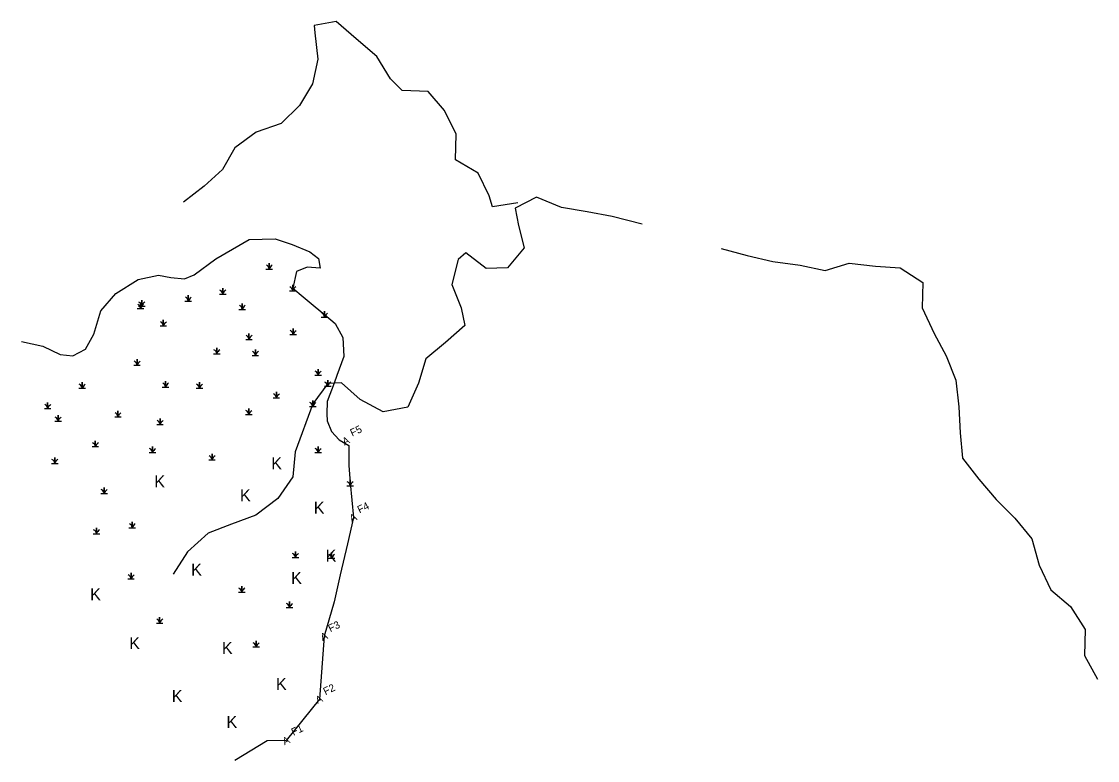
# Model space of a CAD drawing. Extents: x 2171061 to 2188174, y 801741 to 821647.
# Drawn here: x 2186425 to 2187134, y 817904 to 818392 of the extents above; entities that cross this region are included whole.
import ezdxf

# ---------------------------------------------------------------- set-up
doc = ezdxf.new("R2010")
doc.units = 0
for name, color, linetype in [('Exist Environmental Wetland Boundary', 7, 'Continuous'), ('Exist Hydro Jurisdictional Stream or Body of Water NEU Mitigable', 7, 'Continuous'), ('Exist Hydro Swamp or Marsh', 7, 'Continuous'), ('Old_Level_10', 7, 'Continuous'), ('Old_Level_20', 7, 'Continuous'), ('Old_Level_61', 7, 'Continuous')]:
    doc.layers.add(name, color=color, linetype=linetype)

msp = doc.modelspace()

# ---------------------------------------------------------------- linework, layer by layer
at = {"layer": 'Exist Environmental Wetland Boundary'}
msp.add_lwpolyline([(2186425.42, 818180.61), (2186439.36, 818177.5), (2186450.84, 818172.08), (2186459.21, 818171.26), (2186467.58, 818175.69), (2186473.15, 818185.54), (2186477.75, 818200.79), (2186487.59, 818212.27), (2186502.19, 818221.62), (2186515.64, 818224.41), (2186523.68, 818222.94), (2186532.7, 818221.95), (2186539.26, 818224.58), (2186553.53, 818235.24), (2186553.53, 818235.24), (2186575.35, 818247.87), (2186592.58, 818248.36), (2186603.73, 818244.59), (2186615.38, 818239.83), (2186621.12, 818235.4), (2186622.1, 818229.01), (2186613.57, 818229.66), (2186606.52, 818226.87), (2186604.06, 818215.88), (2186610.95, 818210.14), (2186618.82, 818203.58), (2186625.06, 818198.49), (2186631.95, 818192.59), (2186637.03, 818183.24), (2186637.69, 818170.77), (2186633.09, 818158.3), (2186631.29, 818153.22), (2186626.86, 818141.08), (2186626.53, 818133.04), (2186626.86, 818128.29), (2186629.65, 818121.4), (2186634.74, 818115.82), (2186640.97, 818112.04), (2186641.08, 818098.82), (2186641.89, 818087.39), (2186644.07, 818064.67), (2186644.07, 818064.67), (2186640.26, 818047.38), (2186635.37, 818026.96), (2186631.29, 818009), (2186624.86, 817986.4), (2186621.62, 817944.9), (2186599.84, 817917.73), (2186587.16, 817917.49), (2186566.03, 817904.48)], dxfattribs=at)
at = {"layer": 'Exist Hydro Jurisdictional Stream or Body of Water NEU Mitigable'}
for points in [[(2186752.35, 818271.99), (2186735.78, 818269.36), (2186733.49, 818276.58), (2186726.27, 818291.67), (2186711.34, 818300.36), (2186711.67, 818317.26), (2186704.12, 818332.84), (2186693.3, 818345.48), (2186676.24, 818346.13), (2186668.53, 818353.84), (2186659.5, 818368.44), (2186645.89, 818380.09), (2186632.6, 818391.57), (2186618.24, 818388.84), (2186618.66, 818384.19), (2186620.63, 818366.8), (2186617.02, 818350.4), (2186608.49, 818336.13), (2186596.51, 818324.31), (2186579.94, 818318.57), (2186566, 818308.4), (2186557.8, 818294.13), (2186545.82, 818283.14), (2186532.04, 818272.48)], [(2186834.21, 818258.04), (2186814.52, 818263.13), (2186798.12, 818266.08), (2186781.06, 818269.03), (2186764.66, 818275.76), (2186750.55, 818268.54), (2186752.85, 818257.22), (2186756.62, 818242.29), (2186745.63, 818229.17), (2186731.52, 818228.68), (2186718.23, 818239.01), (2186712.98, 818234.75), (2186708.88, 818218.18), (2186715.12, 818202.92), (2186717.41, 818191.28), (2186704.62, 818179.96), (2186691.82, 818169.3), (2186686.9, 818153.22), (2186680.01, 818137.31), (2186663.77, 818134.35), (2186648.51, 818142.39), (2186636.21, 818153.38), (2186627.19, 818153.06), (2186617.35, 818139.6), (2186605.7, 818107.94), (2186604.06, 818091.54), (2186594.38, 818077.27), (2186579.78, 818066.28), (2186563.71, 818060.21), (2186548.28, 818054.3), (2186534.83, 818042), (2186525.32, 818027.4)], [(2186886.37, 818241.97), (2186903.43, 818237.37), (2186920.33, 818233.44), (2186938.38, 818230.98), (2186954.94, 818227.53), (2186970.69, 818232.29), (2186987.92, 818230.32), (2187004.32, 818229.17), (2187019.08, 818219.49), (2187018.76, 818202.76), (2187026.63, 818185.86), (2187034.5, 818171.1), (2187040.9, 818155.19), (2187042.87, 818137.64), (2187043.69, 818120.41), (2187045.33, 818103.68), (2187055.99, 818089.9), (2187067.48, 818076.45), (2187079.78, 818064.31), (2187091.1, 818050.69), (2187095.86, 818033.14), (2187103.57, 818017.06), (2187116.36, 818006.07), (2187126.04, 817990.82), (2187125.71, 817973.76), (2187134.24, 817958.17)]]:
    msp.add_lwpolyline(points, dxfattribs=at)
at = {"layer": 'Exist Hydro Swamp or Marsh'}
for p, q in [((2186588.61, 818230.18), (2186588.61, 818230.18)), ((2186558, 818213.68), (2186558, 818213.68)), ((2186604.06, 818215.88), (2186604.06, 818215.88)), ((2186503.85, 818204.25), (2186503.85, 818204.25)), ((2186504.63, 818205.82), (2186504.63, 818205.82)), ((2186535.24, 818208.97), (2186535.24, 818208.97)), ((2186570.81, 818203.61), (2186570.81, 818203.61)), ((2186625.06, 818198.49), (2186625.06, 818198.49)), ((2186518.84, 818192.78), (2186518.84, 818192.78)), ((2186575.27, 818183.83), (2186575.27, 818183.83)), ((2186604.31, 818186.97), (2186604.31, 818186.97)), ((2186554.08, 818174.4), (2186554.08, 818174.4)), ((2186579.47, 818173.27), (2186579.47, 818173.27)), ((2186501.52, 818166.77), (2186501.52, 818166.77)), ((2186620.79, 818160.26), (2186620.79, 818160.26)), ((2186620.79, 818160.26), (2186620.79, 818160.26)), ((2186465.39, 818151.61), (2186465.39, 818151.61)), ((2186520.33, 818152.4), (2186520.33, 818152.4)), ((2186542.66, 818151.6), (2186542.66, 818151.6)), ((2186627.19, 818153.06), (2186627.19, 818153.06)), ((2186593.32, 818145.33), (2186593.32, 818145.33)), ((2186442.63, 818138.26), (2186442.63, 818138.26)), ((2186488.94, 818132.76), (2186488.94, 818132.76)), ((2186575.14, 818134.26), (2186575.14, 818134.26)), ((2186617.35, 818139.6), (2186617.35, 818139.6)), ((2186449.55, 818129.92), (2186449.55, 818129.92)), ((2186516.68, 818127.75), (2186516.68, 818127.75)), ((2186474.03, 818113.12), (2186474.03, 818113.12)), ((2186511.7, 818109.19), (2186511.7, 818109.19)), ((2186550.94, 818104.48), (2186550.94, 818104.48)), ((2186620.79, 818109.19), (2186620.79, 818109.19)), ((2186447.34, 818102.12), (2186447.34, 818102.12)), ((2186641.89, 818087.39), (2186641.89, 818087.39)), ((2186479.87, 818082.24), (2186479.87, 818082.24)), ((2186479.87, 818082.24), (2186479.87, 818082.24)), ((2186474.81, 818055.77), (2186474.81, 818055.77)), ((2186498.36, 818059.69), (2186498.36, 818059.69)), ((2186605.88, 818040.05), (2186605.88, 818040.05)), ((2186629.68, 818039.51), (2186629.68, 818039.51)), ((2186497.57, 818025.91), (2186497.57, 818025.91)), ((2186570.56, 818017.27), (2186570.56, 818017.27)), ((2186601.96, 818007.06), (2186601.96, 818007.06)), ((2186516.41, 817996.84), (2186516.41, 817996.84)), ((2186579.98, 817981.13), (2186579.98, 817981.13))]:
    msp.add_line(p, q, dxfattribs=at)
for points in [[(2186586.46, 818228.4), (2186588.61, 818228.4), (2186588.61, 818232.34), (2186588.61, 818228.4), (2186590.76, 818228.4)], [(2186601.91, 818214.1), (2186604.06, 818214.1), (2186604.06, 818218.05), (2186604.06, 818214.1), (2186606.21, 818214.1)], [(2186533.09, 818207.18), (2186535.24, 818207.18), (2186535.24, 818211.13), (2186535.24, 818207.18), (2186537.39, 818207.18)], [(2186555.85, 818211.9), (2186558, 818211.9), (2186558, 818215.84), (2186558, 818211.9), (2186560.15, 818211.9)], [(2186501.7, 818202.47), (2186503.85, 818202.47), (2186503.85, 818206.41), (2186503.85, 818202.47), (2186506, 818202.47)], [(2186502.48, 818204.04), (2186504.63, 818204.04), (2186504.63, 818207.99), (2186504.63, 818204.04), (2186506.79, 818204.04)], [(2186568.66, 818201.83), (2186570.81, 818201.83), (2186570.81, 818205.78), (2186570.81, 818201.83), (2186572.96, 818201.83)], [(2186622.91, 818196.71), (2186625.06, 818196.71), (2186625.06, 818200.66), (2186625.06, 818196.71), (2186627.21, 818196.71)], [(2186516.69, 818190.99), (2186518.84, 818190.99), (2186518.84, 818194.94), (2186518.84, 818190.99), (2186520.99, 818190.99)], [(2186573.12, 818182.04), (2186575.27, 818182.04), (2186575.27, 818185.99), (2186575.27, 818182.04), (2186577.42, 818182.04)], [(2186602.16, 818185.19), (2186604.31, 818185.19), (2186604.31, 818189.13), (2186604.31, 818185.19), (2186606.46, 818185.19)], [(2186551.93, 818172.62), (2186554.08, 818172.62), (2186554.08, 818176.56), (2186554.08, 818172.62), (2186556.23, 818172.62)], [(2186577.32, 818171.49), (2186579.47, 818171.49), (2186579.47, 818175.43), (2186579.47, 818171.49), (2186581.62, 818171.49)], [(2186499.37, 818164.98), (2186501.52, 818164.98), (2186501.52, 818168.93), (2186501.52, 818164.98), (2186503.67, 818164.98)], [(2186618.64, 818158.47), (2186620.79, 818158.47), (2186620.79, 818162.42), (2186620.79, 818158.47), (2186622.94, 818158.47)], [(2186618.64, 818158.47), (2186620.79, 818158.47), (2186620.79, 818162.42), (2186620.79, 818158.47), (2186622.94, 818158.47)], [(2186518.18, 818150.62), (2186520.33, 818150.62), (2186520.33, 818154.56), (2186520.33, 818150.62), (2186522.48, 818150.62)], [(2186625.04, 818151.27), (2186627.19, 818151.27), (2186627.19, 818155.22), (2186627.19, 818151.27), (2186629.34, 818151.27)], [(2186463.24, 818149.83), (2186465.39, 818149.83), (2186465.39, 818153.78), (2186465.39, 818149.83), (2186467.54, 818149.83)], [(2186540.51, 818149.81), (2186542.66, 818149.81), (2186542.66, 818153.76), (2186542.66, 818149.81), (2186544.81, 818149.81)], [(2186591.17, 818143.55), (2186593.32, 818143.55), (2186593.32, 818147.49), (2186593.32, 818143.55), (2186595.47, 818143.55)], [(2186440.48, 818136.48), (2186442.63, 818136.48), (2186442.63, 818140.42), (2186442.63, 818136.48), (2186444.78, 818136.48)], [(2186615.2, 818137.82), (2186617.35, 818137.82), (2186617.35, 818141.77), (2186617.35, 818137.82), (2186619.5, 818137.82)], [(2186486.79, 818130.98), (2186488.94, 818130.98), (2186488.94, 818134.92), (2186488.94, 818130.98), (2186491.09, 818130.98)], [(2186572.99, 818132.47), (2186575.14, 818132.47), (2186575.14, 818136.42), (2186575.14, 818132.47), (2186577.29, 818132.47)], [(2186447.4, 818128.14), (2186449.55, 818128.14), (2186449.55, 818132.08), (2186449.55, 818128.14), (2186451.7, 818128.14)], [(2186514.53, 818125.97), (2186516.68, 818125.97), (2186516.68, 818129.92), (2186516.68, 818125.97), (2186518.83, 818125.97)], [(2186471.88, 818111.34), (2186474.03, 818111.34), (2186474.03, 818115.28), (2186474.03, 818111.34), (2186476.18, 818111.34)], [(2186509.55, 818107.41), (2186511.7, 818107.41), (2186511.7, 818111.35), (2186511.7, 818107.41), (2186513.85, 818107.41)], [(2186548.79, 818102.69), (2186550.94, 818102.69), (2186550.94, 818106.64), (2186550.94, 818102.69), (2186553.09, 818102.69)], [(2186618.64, 818107.41), (2186620.79, 818107.41), (2186620.79, 818111.35), (2186620.79, 818107.41), (2186622.94, 818107.41)], [(2186445.19, 818100.34), (2186447.34, 818100.34), (2186447.34, 818104.28), (2186447.34, 818100.34), (2186449.49, 818100.34)], [(2186477.72, 818080.45), (2186479.87, 818080.45), (2186479.87, 818084.4), (2186479.87, 818080.45), (2186482.02, 818080.45)], [(2186477.72, 818080.45), (2186479.87, 818080.45), (2186479.87, 818084.4), (2186479.87, 818080.45), (2186482.02, 818080.45)], [(2186639.74, 818085.61), (2186641.9, 818085.61), (2186641.9, 818089.55), (2186641.9, 818085.61), (2186644.05, 818085.61)], [(2186472.66, 818053.98), (2186474.81, 818053.98), (2186474.81, 818057.93), (2186474.81, 818053.98), (2186476.96, 818053.98)], [(2186496.21, 818057.91), (2186498.36, 818057.91), (2186498.36, 818061.86), (2186498.36, 818057.91), (2186500.51, 818057.91)], [(2186603.73, 818038.27), (2186605.88, 818038.27), (2186605.88, 818042.22), (2186605.88, 818038.27), (2186608.03, 818038.27)], [(2186627.53, 818037.73), (2186629.68, 818037.73), (2186629.68, 818041.68), (2186629.68, 818037.73), (2186631.83, 818037.73)], [(2186495.42, 818024.13), (2186497.57, 818024.13), (2186497.57, 818028.07), (2186497.57, 818024.13), (2186499.72, 818024.13)], [(2186568.41, 818015.49), (2186570.56, 818015.49), (2186570.56, 818019.43), (2186570.56, 818015.49), (2186572.71, 818015.49)], [(2186599.81, 818005.27), (2186601.96, 818005.27), (2186601.96, 818009.22), (2186601.96, 818005.27), (2186604.11, 818005.27)], [(2186514.26, 817995.06), (2186516.41, 817995.06), (2186516.41, 817999.01), (2186516.41, 817995.06), (2186518.56, 817995.06)], [(2186577.83, 817979.35), (2186579.98, 817979.35), (2186579.98, 817983.29), (2186579.98, 817979.35), (2186582.13, 817979.35)]]:
    msp.add_lwpolyline(points, dxfattribs=at)
for centre, radius, start, end in [((2186585.55, 818228.17), 3.07, 4.14034, 67.53497), ((2186593.17, 818226.88), 4.81, 122.12745, 161.62219), ((2186554.94, 818211.68), 3.07, 4.14034, 67.53497), ((2186562.56, 818210.38), 4.81, 122.12745, 161.62219), ((2186600.99, 818213.88), 3.07, 4.14034, 67.53497), ((2186608.62, 818212.59), 4.81, 122.12745, 161.62219), ((2186500.78, 818202.25), 3.07, 4.14034, 67.53497), ((2186501.57, 818203.82), 3.07, 4.14034, 67.53497), ((2186508.41, 818200.95), 4.81, 122.12745, 161.62219), ((2186509.2, 818202.53), 4.81, 122.12745, 161.62219), ((2186532.18, 818206.96), 3.07, 4.14034, 67.53497), ((2186539.8, 818205.67), 4.81, 122.12745, 161.62219), ((2186567.74, 818201.61), 3.07, 4.14034, 67.53497), ((2186575.37, 818200.32), 4.81, 122.12745, 161.62219), ((2186621.99, 818196.49), 3.07, 4.14034, 67.53497), ((2186629.62, 818195.2), 4.81, 122.12745, 161.62219), ((2186515.77, 818190.77), 3.07, 4.14034, 67.53497), ((2186523.4, 818189.48), 4.81, 122.12745, 161.62219), ((2186572.2, 818181.82), 3.07, 4.14034, 67.53497), ((2186579.83, 818180.53), 4.81, 122.12745, 161.62219), ((2186601.24, 818184.96), 3.07, 4.14034, 67.53497), ((2186608.87, 818183.67), 4.81, 122.12745, 161.62219), ((2186551.01, 818172.39), 3.07, 4.14034, 67.53497), ((2186558.64, 818171.1), 4.81, 122.12745, 161.62219), ((2186576.4, 818171.26), 3.07, 4.14034, 67.53497), ((2186584.03, 818169.97), 4.81, 122.12745, 161.62219), ((2186498.45, 818164.76), 3.07, 4.14034, 67.53497), ((2186506.08, 818163.47), 4.81, 122.12745, 161.62219), ((2186617.73, 818158.25), 3.07, 4.14034, 67.53497), ((2186617.73, 818158.25), 3.07, 4.14034, 67.53497), ((2186625.35, 818156.96), 4.81, 122.12745, 161.62219), ((2186625.35, 818156.96), 4.81, 122.12745, 161.62219), ((2186462.33, 818149.61), 3.07, 4.14034, 67.53497), ((2186469.95, 818148.32), 4.81, 122.12745, 161.62219), ((2186517.27, 818150.4), 3.07, 4.14034, 67.53497), ((2186524.89, 818149.1), 4.81, 122.12745, 161.62219), ((2186539.59, 818149.59), 3.07, 4.14034, 67.53497), ((2186547.22, 818148.3), 4.81, 122.12745, 161.62219), ((2186624.12, 818151.05), 3.07, 4.14034, 67.53497), ((2186631.75, 818149.76), 4.81, 122.12745, 161.62219), ((2186590.26, 818143.32), 3.07, 4.14034, 67.53497), ((2186597.88, 818142.03), 4.81, 122.12745, 161.62219), ((2186614.28, 818137.6), 3.07, 4.14034, 67.53497), ((2186621.91, 818136.31), 4.81, 122.12745, 161.62219), ((2186439.57, 818136.25), 3.07, 4.14034, 67.53497), ((2186447.19, 818134.96), 4.81, 122.12745, 161.62219), ((2186485.87, 818130.75), 3.07, 4.14034, 67.53497), ((2186493.5, 818129.46), 4.81, 122.12745, 161.62219), ((2186572.07, 818132.25), 3.07, 4.14034, 67.53497), ((2186579.7, 818130.96), 4.81, 122.12745, 161.62219), ((2186446.49, 818127.92), 3.07, 4.14034, 67.53497), ((2186454.11, 818126.62), 4.81, 122.12745, 161.62219), ((2186513.61, 818125.75), 3.07, 4.14034, 67.53497), ((2186521.24, 818124.45), 4.81, 122.12745, 161.62219), ((2186470.96, 818111.11), 3.07, 4.14034, 67.53497), ((2186478.59, 818109.82), 4.81, 122.12745, 161.62219), ((2186508.63, 818107.18), 3.07, 4.14034, 67.53497), ((2186516.26, 818105.89), 4.81, 122.12745, 161.62219), ((2186547.87, 818102.47), 3.07, 4.14034, 67.53497), ((2186555.5, 818101.18), 4.81, 122.12745, 161.62219), ((2186617.73, 818107.18), 3.07, 4.14034, 67.53497), ((2186625.35, 818105.89), 4.81, 122.12745, 161.62219), ((2186444.27, 818100.11), 3.07, 4.14034, 67.53497), ((2186451.9, 818098.82), 4.81, 122.12745, 161.62219), ((2186638.83, 818085.38), 3.07, 4.14034, 67.53497), ((2186646.46, 818084.09), 4.81, 122.12745, 161.62219), ((2186476.8, 818080.23), 3.07, 4.14034, 67.53497), ((2186476.8, 818080.23), 3.07, 4.14034, 67.53497), ((2186484.43, 818078.94), 4.81, 122.12745, 161.62219), ((2186484.43, 818078.94), 4.81, 122.12745, 161.62219), ((2186471.74, 818053.76), 3.07, 4.14034, 67.53497), ((2186479.37, 818052.47), 4.81, 122.12745, 161.62219), ((2186495.29, 818057.69), 3.07, 4.14034, 67.53497), ((2186502.92, 818056.4), 4.81, 122.12745, 161.62219), ((2186602.81, 818038.05), 3.07, 4.14034, 67.53497), ((2186610.44, 818036.76), 4.81, 122.12745, 161.62219), ((2186626.61, 818037.51), 3.07, 4.14034, 67.53497), ((2186634.24, 818036.22), 4.81, 122.12745, 161.62219), ((2186494.5, 818023.91), 3.07, 4.14034, 67.53497), ((2186502.13, 818022.61), 4.81, 122.12745, 161.62219), ((2186567.5, 818015.26), 3.07, 4.14034, 67.53497), ((2186575.12, 818013.97), 4.81, 122.12745, 161.62219), ((2186598.89, 818005.05), 3.07, 4.14034, 67.53497), ((2186606.52, 818003.76), 4.81, 122.12745, 161.62219), ((2186513.34, 817994.84), 3.07, 4.14034, 67.53497), ((2186520.97, 817993.54), 4.81, 122.12745, 161.62219), ((2186576.91, 817979.13), 3.07, 4.14034, 67.53497), ((2186584.54, 817977.83), 4.81, 122.12745, 161.62219)]:
    msp.add_arc(centre, radius, start, end, dxfattribs=at)

# ---------------------------------------------------------------- texts
at = {"layer": 'Old_Level_10'}
for p in [(2186589.9, 818096.44), (2186512.92, 818084.46), (2186569.36, 818075.38), (2186617.95, 818067.17), (2186625.74, 818035.58), (2186537.19, 818026.39), (2186603.05, 818020.92), (2186470.64, 818010.13), (2186496.4, 817977.89), (2186557.43, 817974.74), (2186593.06, 817950.98), (2186524.38, 817943), (2186560.47, 817925.98)]:
    msp.add_text('K', height=7.87, dxfattribs=at).set_placement(p)
at = {"layer": 'Old_Level_20'}
for p in [(2186638.15, 818112), (2186642.92, 818061.39), (2186623.71, 817983.11), (2186620.47, 817941.61), (2186598.69, 817914.44)]:
    msp.add_text('A', height=4.92, rotation=25.73197, dxfattribs=at).set_placement(p)
at = {"layer": 'Old_Level_61'}
for s, p in [('F5', (2186643.32, 818117.89)), ('F4', (2186648.09, 818067.28)), ('F3', (2186628.88, 817989)), ('F2', (2186625.63, 817947.5)), ('F1', (2186604.6, 817920.69))]:
    msp.add_text(s, height=4.921, rotation=25.73197, dxfattribs=at).set_placement(p)

doc.saveas('drawing.dxf')
